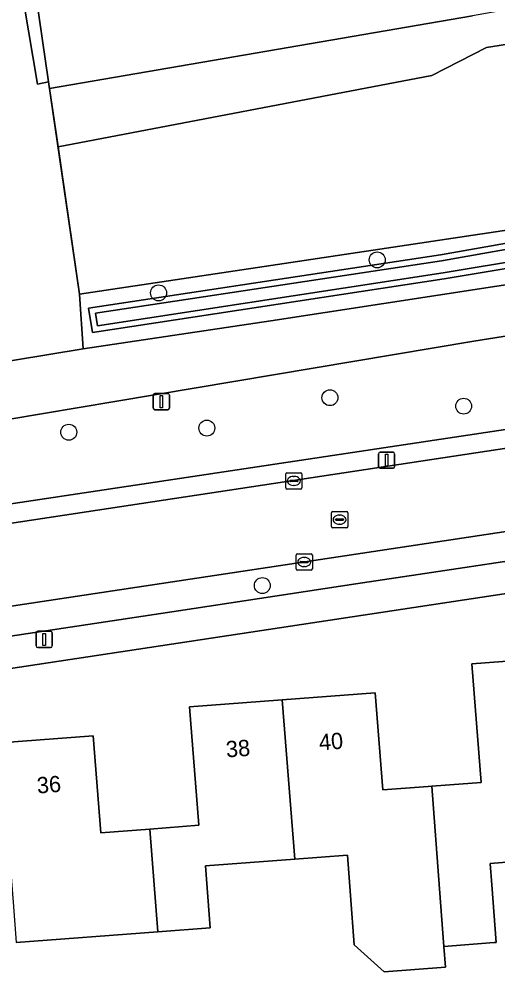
# Model space of a CAD drawing. Extents: x 163426 to 164192, y 380329 to 381641.
# Drawn here: x 163735.1 to 163764.5, y 380963.7 to 381022.4 of the extents above; entities that cross this region are included whole.
import ezdxf

# ---------------------------------------------------------------- set-up
doc = ezdxf.new("R2010")
doc.units = 0
for name, color, linetype in [('IMGEO_Boom', 7, 'Continuous'), ('IMGEO_Erf', 7, 'Continuous'), ('IMGEO_Fietspad_gesloten', 7, 'Continuous'), ('IMGEO_Groenvoorziening', 7, 'Continuous'), ('IMGEO_Hek', 7, 'Continuous'), ('IMGEO_Kolk', 7, 'Continuous'), ('IMGEO_Lichtmast', 7, 'Continuous'), ('IMGEO_Oever', 7, 'Continuous'), ('IMGEO_Pand', 7, 'Continuous'), ('IMGEO_Pand_nummerreeks', 7, 'Continuous'), ('IMGEO_Parkeervlak_open', 7, 'Continuous'), ('IMGEO_Rijbaan_lokaal_halfverhard', 7, 'Continuous'), ('IMGEO_Rijbaan_lokaal_open', 7, 'Continuous'), ('IMGEO_Rioolput', 7, 'Continuous'), ('IMGEO_Voetpad_halfverhard', 7, 'Continuous'), ('IMGEO_Voetpad_open', 7, 'Continuous'), ('IMGEO_Waterloop', 7, 'Continuous')]:
    doc.layers.add(name, color=color, linetype=linetype)

msp = doc.modelspace()

# ---------------------------------------------------------------- linework, layer by layer
at = {"layer": 'IMGEO_Boom'}
for centre in [(163757.128, 381007.539), (163743.686, 381005.508), (163754.222, 380999.062), (163762.443, 380998.54), (163738.164, 380996.938), (163746.65, 380997.193), (163750.062, 380987.506)]:
    msp.add_circle(centre, 0.489, dxfattribs=at)
at = {"layer": 'IMGEO_Erf'}
for points in [[(163791.615, 380991.037), (163706.397, 380978.148), (163706.124, 380980.097), (163700.884, 380980.954), (163698.7, 380981.311)], [(163733.965, 380977.826), (163739.669, 380978.257), (163740.14, 380972.293), (163743.151, 380972.531), (163746.154, 380972.768), (163745.579, 380980.046), (163751.293, 380980.48), (163757.011, 380980.915), (163757.474, 380974.935), (163760.256, 380975.15), (163760.495, 380975.169), (163763.514, 380975.402), (163762.95, 380982.688), (163768.663, 380983.126), (163774.338, 380983.562), (163774.789, 380977.583), (163777.81, 380977.811), (163780.838, 380978.04), (163780.287, 380985.334), (163785.995, 380985.769), (163791.706, 380986.205), (163791.973, 380982.515), (163795.041, 380982.737), (163794.622, 380988.465)], [(163766.342, 380970.588), (163764.071, 380970.415), (163764.171, 380969.1), (163764.441, 380965.553), (163764.312, 380965.543), (163761.23, 380965.308), (163761.328, 380964.027), (163757.558, 380963.739), (163755.718, 380965.399), (163755.486, 380968.438), (163755.296, 380970.928), (163752.055, 380970.681), (163746.571, 380970.263), (163746.861, 380966.459), (163743.64, 380966.213), (163734.939, 380965.55)]]:
    msp.add_lwpolyline(points, dxfattribs=at)
at = {"layer": 'IMGEO_Fietspad_gesloten'}
msp.add_lwpolyline([(163798.617, 381008.195), (163802.117, 381008.461), (163803.909, 381008.598), (163837.358, 381011.143), (163841.843, 381011.436), (163841.646, 381014.473), (163798.95, 381011.221), (163750.595, 381003.795), (163739.058, 381002.067), (163726.494, 381000), (163720.063, 380998.942), (163713.882, 380997.77), (163709.32, 380997.059), (163710.283, 380993.655), (163740.992, 380998.833), (163763.066, 381002.537)], close=True, dxfattribs=at)
at = {"layer": 'IMGEO_Groenvoorziening'}
for points in [[(163822.563, 381029.927), (163763.854, 381020.612), (163760.495, 381018.888), (163737.506, 381014.49), (163738.82, 381005.439), (163794.886, 381013.846), (163795.15, 381013.89), (163797.645, 381014.335), (163800.272, 381014.541), (163803.735, 381014.854), (163820.166, 381016.094), (163832.877, 381017.087), (163835.244, 381016.916), (163841.691, 381017.267), (163841.374, 381020.725), (163839.519, 381040.942)], [(163722.892, 381005.628), (163720.37, 381021.803), (163734.556, 381028.338), (163736.243, 381018.347), (163736.925, 381018.494), (163735.177, 381030.533), (163734.21, 381030.15), (163718.354, 381023.204), (163718.123, 381021.061), (163711.744, 381019.032), (163712.418, 381016.816), (163711.092, 381016.421), (163718.847, 381014.319), (163716.497, 381006.94), (163704.558, 381003.26), (163704.722, 381002.743), (163705.546, 381000), (163706.241, 380997.685), (163709.32, 380997.059), (163713.882, 380997.77), (163720.063, 380998.942), (163721.324, 381000)], [(163735.177, 381030.533), (163736.925, 381018.494), (163736.984, 381018.089), (163762.988, 381022.55)], [(163832.964, 381015.283), (163797.885, 381012.478), (163761.245, 381006.381), (163739.631, 381003.064), (163739.378, 381004.564), (163761.025, 381007.844), (163794.886, 381013.846), (163738.82, 381005.439), (163739.058, 381002.067), (163750.595, 381003.795), (163798.95, 381011.221), (163841.646, 381014.473)], [(163784.239, 381000), (163802.549, 381002.756), (163802.117, 381008.461), (163798.617, 381008.195), (163763.066, 381002.537), (163740.992, 380998.833), (163710.283, 380993.655), (163707.734, 380992.722), (163707.816, 380992.446)], [(163713.192, 380989.306), (163784.239, 381000)]]:
    msp.add_lwpolyline(points, dxfattribs=at)
at = {"layer": 'IMGEO_Hek'}
for points in [[(163736.925, 381018.494), (163735.177, 381030.533)], [(163738.82, 381005.439), (163736.925, 381018.494)], [(163794.886, 381013.846), (163738.82, 381005.439)]]:
    msp.add_lwpolyline(points, dxfattribs=at)
at = {"layer": 'IMGEO_Kolk'}
for p, q in [((163751.501, 380993.517), (163751.501, 380994.369)), ((163751.576, 380994.443), (163752.428, 380994.443)), ((163752.502, 380994.369), (163752.502, 380993.517)), ((163751.76, 380993.937), (163751.76, 380993.949)), ((163752.198, 380993.9), (163751.8, 380993.9)), ((163751.803, 380993.986), (163752.201, 380993.986)), ((163751.989, 380994.223), (163752.014, 380994.223)), ((163752.244, 380993.949), (163752.244, 380993.937)), ((163752.428, 380993.443), (163751.576, 380993.443)), ((163752.012, 380993.663), (163751.987, 380993.663)), ((163752.139, 380988.527), (163752.139, 380989.379)), ((163752.214, 380989.453), (163753.066, 380989.453)), ((163752.441, 380988.996), (163752.839, 380988.996)), ((163752.627, 380989.233), (163752.652, 380989.233)), ((163753.14, 380989.379), (163753.14, 380988.527)), ((163753.066, 380988.453), (163752.214, 380988.453)), ((163752.398, 380988.947), (163752.398, 380988.959)), ((163752.836, 380988.91), (163752.438, 380988.91)), ((163752.65, 380988.673), (163752.625, 380988.673)), ((163752.882, 380988.959), (163752.882, 380988.947))]:
    msp.add_line(p, q, dxfattribs=at)
for points in [[(163751.501, 380993.517), (163751.501, 380994.369)], [(163751.576, 380994.443), (163752.428, 380994.443)], [(163752.502, 380994.369), (163752.502, 380993.517)], [(163752.428, 380993.443), (163751.576, 380993.443)], [(163752.139, 380988.527), (163752.139, 380989.379)], [(163752.214, 380989.453), (163753.066, 380989.453)], [(163753.14, 380989.379), (163753.14, 380988.527)], [(163753.066, 380988.453), (163752.214, 380988.453)]]:
    msp.add_lwpolyline(points, dxfattribs=at)
for centre, radius, start, end in [((163751.578, 380994.367), 0.0765, 91.55205, 178.44795), ((163751.578, 380994.367), 0.0765, 91.55205, 178.44795), ((163752.426, 380994.367), 0.0765, 1.55205, 88.44795), ((163752.426, 380994.367), 0.0765, 1.55205, 88.44795), ((163751.8, 380993.946), 0.0403, 85.87752, 175.75265), ((163751.797, 380993.936), 0.0366, 178.93798, 274.71019), ((163752.201, 380993.943), 0.043, 264.86636, 352.45326), ((163752.205, 380993.948), 0.0386, 1.73085, 96.63898), ((163751.578, 380993.519), 0.0765, 181.55205, 268.44795), ((163751.578, 380993.519), 0.0765, 181.55205, 268.44795), ((163752.426, 380993.519), 0.0765, 271.55205, 358.44795), ((163752.426, 380993.519), 0.0765, 271.55205, 358.44795), ((163752.216, 380989.377), 0.0765, 91.55205, 178.44795), ((163752.216, 380989.377), 0.0765, 91.55205, 178.44795), ((163752.438, 380988.956), 0.0403, 85.87752, 175.75265), ((163752.843, 380988.958), 0.0386, 1.73085, 96.63898), ((163753.064, 380989.377), 0.0765, 1.55205, 88.44795), ((163753.064, 380989.377), 0.0765, 1.55205, 88.44795), ((163752.216, 380988.529), 0.0765, 181.55205, 268.44795), ((163752.216, 380988.529), 0.0765, 181.55205, 268.44795), ((163752.435, 380988.946), 0.0366, 178.93798, 274.71019), ((163752.839, 380988.953), 0.043, 264.86636, 352.45326), ((163753.064, 380988.529), 0.0765, 271.55205, 358.44795), ((163753.064, 380988.529), 0.0765, 271.55205, 358.44795)]:
    msp.add_arc(centre, radius, start, end, dxfattribs=at)
for centre, major_axis, ratio, start_param, end_param in [((163751.988, 380993.943), (-0.387, 0.002), 0.722429, 4.712389, 7.853982), ((163752.013, 380993.943), (-0.39, 0.002), 0.717154, 1.570796, 4.712389), ((163752.626, 380988.953), (-0.387, 0.002), 0.722429, 4.712389, 7.853982), ((163752.651, 380988.953), (-0.39, 0.002), 0.717154, 1.570796, 4.712389)]:
    msp.add_ellipse(centre, major_axis=major_axis, ratio=ratio, start_param=start_param, end_param=end_param, dxfattribs=at)
at = {"layer": 'IMGEO_Lichtmast'}
for p, q in [((163743.357, 380998.419), (163743.357, 380999.219)), ((163743.357, 380999.219), (163743.357, 380998.419)), ((163743.457, 380999.319), (163744.247, 380999.319)), ((163744.247, 380999.319), (163743.457, 380999.319)), ((163744.347, 380999.219), (163744.347, 380998.419)), ((163744.347, 380998.419), (163744.347, 380999.219)), ((163744.247, 380998.319), (163743.457, 380998.319)), ((163743.457, 380998.319), (163744.247, 380998.319)), ((163757.209, 380994.819), (163757.209, 380995.619)), ((163757.209, 380995.619), (163757.209, 380994.819)), ((163757.309, 380995.719), (163758.099, 380995.719)), ((163758.099, 380995.719), (163757.309, 380995.719)), ((163758.199, 380995.619), (163758.199, 380994.819)), ((163758.199, 380994.819), (163758.199, 380995.619)), ((163758.099, 380994.719), (163757.309, 380994.719)), ((163757.309, 380994.719), (163758.099, 380994.719)), ((163736.156, 380983.791), (163736.156, 380984.591)), ((163736.156, 380984.591), (163736.156, 380983.791)), ((163736.256, 380984.691), (163737.046, 380984.691)), ((163737.046, 380984.691), (163736.256, 380984.691)), ((163737.146, 380984.591), (163737.146, 380983.791)), ((163737.146, 380983.791), (163737.146, 380984.591)), ((163737.046, 380983.691), (163736.256, 380983.691)), ((163736.256, 380983.691), (163737.046, 380983.691))]:
    msp.add_line(p, q, dxfattribs=at)
for points in [[(163743.777, 380999.194), (163743.927, 380999.194), (163743.927, 380998.444), (163743.777, 380998.444), (163743.777, 380999.194)], [(163757.629, 380995.594), (163757.779, 380995.594), (163757.779, 380994.844), (163757.629, 380994.844), (163757.629, 380995.594)], [(163736.576, 380984.566), (163736.726, 380984.566), (163736.726, 380983.816), (163736.576, 380983.816), (163736.576, 380984.566)]]:
    msp.add_lwpolyline(points, dxfattribs=at)
for centre, start, end in [((163743.457, 380999.219), 90, 180), ((163743.457, 380999.219), 90, 180), ((163744.247, 380999.219), 0, 90), ((163744.247, 380999.219), 360, 90), ((163743.457, 380998.419), 180, 270), ((163743.457, 380998.419), 180, 270), ((163744.247, 380998.419), 270, 0), ((163744.247, 380998.419), 270, 0), ((163757.309, 380995.619), 90, 180), ((163757.309, 380995.619), 90, 180), ((163758.099, 380995.619), 0, 90), ((163758.099, 380995.619), 360, 90), ((163757.309, 380994.819), 180, 270), ((163757.309, 380994.819), 180, 270), ((163758.099, 380994.819), 270, 0), ((163758.099, 380994.819), 270, 0), ((163736.256, 380984.591), 90, 180), ((163736.256, 380984.591), 90, 180), ((163737.046, 380984.591), 0, 90), ((163737.046, 380984.591), 360, 90), ((163736.256, 380983.791), 180, 270), ((163736.256, 380983.791), 180, 270), ((163737.046, 380983.791), 270, 0), ((163737.046, 380983.791), 270, 0)]:
    msp.add_arc(centre, 0.1, start, end, dxfattribs=at)
at = {"layer": 'IMGEO_Oever'}
for points in [[(163832.964, 381015.283), (163841.715, 381015.283), (163841.825, 381016.439), (163835.244, 381016.916), (163832.877, 381017.087), (163820.166, 381016.094), (163803.735, 381014.854), (163800.272, 381014.541), (163797.645, 381014.335), (163795.15, 381013.89), (163794.886, 381013.846), (163761.025, 381007.844), (163739.378, 381004.564), (163739.631, 381003.064), (163761.245, 381006.381), (163797.885, 381012.478)], [(163841.425, 381016.101), (163841.382, 381015.649), (163832.949, 381015.649), (163797.84, 381012.842), (163761.187, 381006.742), (163739.932, 381003.48), (163739.801, 381004.258), (163761.084, 381007.483), (163794.948, 381013.485), (163795.212, 381013.529), (163797.692, 381013.972), (163800.303, 381014.176), (163803.765, 381014.489), (163820.194, 381015.729), (163832.878, 381016.72), (163835.218, 381016.551)]]:
    msp.add_lwpolyline(points, close=True, dxfattribs=at)
at = {"layer": 'IMGEO_Pand'}
for points in [[(163768.663, 380983.126), (163762.95, 380982.688), (163763.514, 380975.402), (163760.495, 380975.169), (163760.96, 380968.855), (163761.23, 380965.308), (163764.312, 380965.543), (163764.441, 380965.553), (163764.171, 380969.1), (163764.071, 380970.415), (163766.342, 380970.588), (163766.152, 380973.078), (163769.393, 380973.325)], [(163760.495, 380975.169), (163760.256, 380975.15), (163757.474, 380974.935), (163757.011, 380980.915), (163751.293, 380980.48), (163752.055, 380970.681), (163755.296, 380970.928), (163755.486, 380968.438), (163755.718, 380965.399), (163757.558, 380963.739), (163761.328, 380964.027), (163761.23, 380965.308), (163760.96, 380968.855)], [(163751.293, 380980.48), (163745.579, 380980.046), (163746.154, 380972.768), (163743.151, 380972.531), (163743.64, 380966.213), (163746.861, 380966.459), (163746.571, 380970.263), (163752.055, 380970.681)], [(163743.151, 380972.531), (163740.14, 380972.293), (163739.669, 380978.257), (163733.965, 380977.826), (163734.75, 380968.04), (163734.939, 380965.55), (163743.64, 380966.213)]]:
    msp.add_lwpolyline(points, close=True, dxfattribs=at)
at = {"layer": 'IMGEO_Parkeervlak_open'}
for points in [[(163790.712, 380994.707), (163718.727, 380983.83)], [(163721.599, 380982.433), (163728.306, 380983.447), (163738.245, 380984.949), (163744.918, 380985.958), (163755.81, 380987.604), (163762.507, 380988.616), (163773.416, 380990.265), (163780.104, 380991.276), (163788.023, 380992.473)]]:
    msp.add_lwpolyline(points, dxfattribs=at)
at = {"layer": 'IMGEO_Rijbaan_lokaal_halfverhard'}
for points in [[(163737.506, 381014.49), (163736.984, 381018.089), (163736.925, 381018.494), (163736.243, 381018.347), (163734.556, 381028.338), (163720.37, 381021.803), (163722.892, 381005.628)], [(163721.324, 381000), (163720.063, 380998.942), (163726.494, 381000), (163739.058, 381002.067), (163738.82, 381005.439), (163737.506, 381014.49)]]:
    msp.add_lwpolyline(points, dxfattribs=at)
at = {"layer": 'IMGEO_Rijbaan_lokaal_open'}
for points in [[(163795.472, 381000.546), (163791.196, 380999.906), (163712.588, 380987.995)], [(163710.476, 380982.61), (163710.722, 380982.646), (163718.727, 380983.83), (163790.712, 380994.707)]]:
    msp.add_lwpolyline(points, dxfattribs=at)
at = {"layer": 'IMGEO_Rioolput'}
for p, q in [((163754.314, 380991.133), (163754.314, 380991.985)), ((163754.389, 380992.059), (163755.241, 380992.059)), ((163755.315, 380991.985), (163755.315, 380991.133)), ((163754.573, 380991.553), (163754.573, 380991.565)), ((163755.011, 380991.516), (163754.613, 380991.516)), ((163754.616, 380991.602), (163755.014, 380991.602)), ((163754.802, 380991.839), (163754.827, 380991.839)), ((163755.057, 380991.565), (163755.057, 380991.553)), ((163755.241, 380991.059), (163754.389, 380991.059)), ((163754.825, 380991.279), (163754.8, 380991.279))]:
    msp.add_line(p, q, dxfattribs=at)
for points in [[(163754.314, 380991.133), (163754.314, 380991.985)], [(163754.389, 380992.059), (163755.241, 380992.059)], [(163755.315, 380991.985), (163755.315, 380991.133)], [(163755.241, 380991.059), (163754.389, 380991.059)]]:
    msp.add_lwpolyline(points, dxfattribs=at)
for centre, radius, start, end in [((163754.391, 380991.983), 0.0765, 91.55205, 178.44795), ((163754.391, 380991.983), 0.0765, 91.55205, 178.44795), ((163755.239, 380991.983), 0.0765, 1.55205, 88.44795), ((163755.239, 380991.983), 0.0765, 1.55205, 88.44795), ((163754.613, 380991.562), 0.0403, 85.87752, 175.75265), ((163754.61, 380991.552), 0.0366, 178.93798, 274.71019), ((163755.014, 380991.559), 0.043, 264.86636, 352.45326), ((163755.018, 380991.564), 0.0386, 1.73085, 96.63898), ((163754.391, 380991.135), 0.0765, 181.55205, 268.44795), ((163754.391, 380991.135), 0.0765, 181.55205, 268.44795), ((163755.239, 380991.135), 0.0765, 271.55205, 358.44795), ((163755.239, 380991.135), 0.0765, 271.55205, 358.44795)]:
    msp.add_arc(centre, radius, start, end, dxfattribs=at)
for centre, major_axis, ratio, start_param, end_param in [((163754.801, 380991.559), (-0.387, 0.002), 0.722429, 4.712389, 7.853982), ((163754.826, 380991.559), (-0.39, 0.002), 0.717154, 1.570796, 4.712389)]:
    msp.add_ellipse(centre, major_axis=major_axis, ratio=ratio, start_param=start_param, end_param=end_param, dxfattribs=at)
at = {"layer": 'IMGEO_Voetpad_halfverhard'}
msp.add_lwpolyline([(163810.663, 381080.58), (163820.163, 381032.72), (163762.988, 381022.55), (163736.984, 381018.089), (163737.506, 381014.49), (163760.495, 381018.888), (163763.854, 381020.612), (163822.563, 381029.927), (163812.477, 381080.889)], close=True, dxfattribs=at)
at = {"layer": 'IMGEO_Voetpad_open'}
for points in [[(163804.54, 381000), (163804.103, 381005.949), (163803.909, 381008.598), (163802.117, 381008.461), (163802.549, 381002.756), (163784.239, 381000), (163713.192, 380989.306)], [(163712.588, 380987.995), (163791.196, 380999.906), (163795.472, 381000.546)], [(163788.023, 380992.473), (163780.104, 380991.276), (163773.416, 380990.265), (163762.507, 380988.616), (163755.81, 380987.604), (163744.918, 380985.958), (163738.245, 380984.949), (163728.306, 380983.447), (163721.599, 380982.433)], [(163698.261, 380989.541), (163700.884, 380980.954), (163706.124, 380980.097), (163706.397, 380978.148), (163791.615, 380991.037)]]:
    msp.add_lwpolyline(points, dxfattribs=at)
at = {"layer": 'IMGEO_Waterloop'}
msp.add_lwpolyline([(163841.425, 381016.101), (163835.218, 381016.551), (163832.878, 381016.72), (163820.194, 381015.729), (163803.765, 381014.489), (163800.303, 381014.176), (163797.692, 381013.972), (163795.212, 381013.529), (163794.948, 381013.485), (163761.084, 381007.483), (163739.801, 381004.258), (163739.932, 381003.48), (163761.187, 381006.742), (163797.84, 381012.842), (163832.949, 381015.649), (163841.382, 381015.649)], close=True, dxfattribs=at)

# ---------------------------------------------------------------- texts
at = {"layer": 'IMGEO_Pand_nummerreeks'}
for s, rotation, p in [('40', 4.34875, (163753.581, 380977.364)), ('38', 4.34696, (163747.865, 380976.93)), ('36', 4.31734, (163736.238, 380974.709))]:
    msp.add_text(s, height=1, rotation=rotation, dxfattribs=at).set_placement(p)

doc.saveas('drawing.dxf')
